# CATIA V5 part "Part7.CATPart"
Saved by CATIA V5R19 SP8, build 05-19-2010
Part number: Part7
Bounding box of the stored display mesh (mm): x -16.811 to 5.183, y 15 to 25, z -46.499 to 12.222
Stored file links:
  G:\IAO\IAO_2010\iao\IAO_MMS_Groupe3\PB\cgourmelen\Projet_IAO_gourmelen_camille\Projet_IAO_gourmelen_camille\Part7.CATPart
  G:\IAO\IAO_2010\iao\IAO_MMS_Groupe3\PB\cgourmelen\Projet_IAO_gourmelen_camille\Projet_IAO_gourmelen_camille\Catia_Gourmelen\squelette total.CATProduct
  G:\IAO\IAO_2010\iao\IAO_MMS_Groupe3\PB\cgourmelen\Projet_IAO_gourmelen_camille\Projet_IAO_gourmelen_camille\Catia_Gourmelen\s-griffe.CATPart
  G:\IAO\IAO_2010\iao\IAO_MMS_Groupe3\PB\cgourmelen\Projet_IAO_gourmelen_camille\Projet_IAO_gourmelen_camille\bati2.CATPart
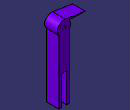
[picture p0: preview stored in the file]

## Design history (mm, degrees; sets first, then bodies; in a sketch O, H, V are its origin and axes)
Set1
  Plane1: linked copy from another document
  Line1: linked copy from another document
Body1 (main body)
  Sketch1 on Plane1, origin (0, 20, 0), H (-1, 0, 0), V (0, 0, 1)
    line L1 (0, -23.4994) -> (-2, -23.4994)
    point P1 (0, -23.4994)
    point P2 (-2, -23.4994)
    line L2 (-2, -23.4994) -> (-2, -46.4994)
    point P3 (-2, -46.4994)
    line L3 (-2, -46.4994) -> (-4, -46.4994)
    point P4 (-4, -46.4994)
    line L4 (-4, -46.4994) -> (-4, 3.5006)
    point P5 (-4, 3.5006)
    point P6 (4, -46.4994)
    point P7 (2, -46.4994)
    line L5 (2, -46.4994) -> (4, -46.4994)
    point P8 (2, -23.4994)
    line L6 (2, -23.4994) -> (2, -46.4994)
    point P9 (0, -23.4994)
    line L7 (0, -23.4994) -> (2, -23.4994)
    point P10 (4, 3.5006)
    line L8 (4, -46.4994) -> (4, 3.5006)
    point P11 (4, 19.4553)
    arc A1 centre (0, 7) radius 5.3146 from (-4, 3.5006) to (0.9898, 12.2217) cw
    point P12 (0, 7)
    line L9 (0.9898, 12.2217) -> (16.8111, 9.6378)
    point P14 (16.8111, 9.6378)
    line L10 (16.8111, 9.6378) -> (4.3313, 10.0798)
    point P15 (16.8111, 9.6378)
    point P16 (4.3313, 10.0798)
    arc A2 centre (0, 7) radius 5.3146 from (4.3313, 10.0798) to (4, 3.5006) cw
    point P17 (0, 7)
    point P18 (5.3123, 6.8427)
    point P19 (4, 3.5006)
    reference projected point E1 (0, 7) from Line1
    circle A3 centre (0, 7) radius 1
    point P20 (0, 7)
    length L3 = 2
    length L1 = 2
    length L4 = 50
    length L6 = 23
    radius A1 = 5.3146
    radius A3 = 1
    coincidence: P1 V, P11 L8, A1 P10, P15 L9, P16 A1, A2 P18, P18 A1, P19 A1, P19 L8, P17 E1, P20 P12, P14 P15, P1 P9, P10 P19
    horizontal: L1 H, L3 H
    vertical: L2 V, L4 V
    symmetry: P4 P6 V, P3 P7 V, L3 L5 V, P2 P8 V, L2 L6 V, P1 P9 V, L1 L7 V, P5 P10 V, L4 L8 V
  Pad1: profile Sketch1, direction (0, 1, 0), length 5, mirrored extent
  Sketch2 on Plane1, origin (0, 20, 0), H (-1, 0, 0), V (0, 0, 1)
    line L1 (0, 36.991) -> (0, -53.9014)
    distance L1 V = 0
    vertical: L1 V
